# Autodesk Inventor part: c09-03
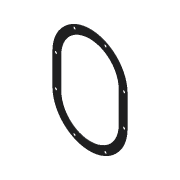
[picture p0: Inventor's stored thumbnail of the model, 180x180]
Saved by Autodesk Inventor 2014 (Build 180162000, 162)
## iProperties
Created: 2010-12
Part Number: c09-03
Material: Rubber
Document SubType Name: Modeling
Designer: Thom Tremblay
Mass: 7.85962 g
Surface Area: 147.076 cm^2
Volume: 8.4512 cm^3
Density: 0.93 g/cm^3
Appearance: Rubber - Black - Version 1.1
Author: Thom Tremblay
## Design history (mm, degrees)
sketch "Sketch1"
  geometry: L1 (-60, 33.338)-(-60, -16.662) reference; L2 (60, -16.662)-(60, 33.338) reference; L3 (-46.998, -16.662)-(-46.998, 33.338) reference; L4 (46.998, 33.338)-(46.998, -16.662) reference; C1 r 1.621 at (-55, -17.463) reference; C2 r 1.621 at (-25, -66.452) reference; C3 r 1.621 at (25, -66.452) reference; C4 r 1.621 at (55, -17.462) reference; C5 r 1.621 at (55, 33.338) reference; C6 r 1.621 at (25, 82.327) reference; C7 r 1.621 at (-25, 82.327) reference; C8 r 1.621 at (-55, 33.337) reference; A1 r 60 centre (0, -16.662) between (-60, -16.662) and (-18.704, -73.673) reference; A2 r 60 centre (0, 33.338) between (60, 33.338) and (-60, 33.338) reference; A3 r 46.998 centre (0, -16.662) between (-46.998, -16.662) and (46.998, -16.662) reference; A4 r 46.998 centre (0, 33.338) between (46.998, 33.338) and (-46.998, 33.338) reference; A5 r 60.082 centre (0, -16.662) between (-16.251, -74.505) and (16.251, -74.505) reference; A6 r 60 centre (0, -16.662) between (18.704, -73.673) and (60, -16.662) reference; 21 further points
extrude "Extrusion1" new body sketch "Sketch1" distance "d0" = 1.27; taper "d1" = 0 deg
node "Hole4"
body "Solid1"
node "Reference1"
sketch "Sketch4"
  geometry: 8 further points
hole "Hole3" sketch "Sketch4" diameter "d16" = 4.49999; stored, may be unused: countersink angle "d20" = 82 deg, drill point angle "d22" = 0 deg; dims "d17" = 19.05, "d18" = 9.525, "d19" = 6.35, "d21" = 25.4
